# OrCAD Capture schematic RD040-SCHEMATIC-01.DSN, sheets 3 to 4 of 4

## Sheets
3 2: size A3
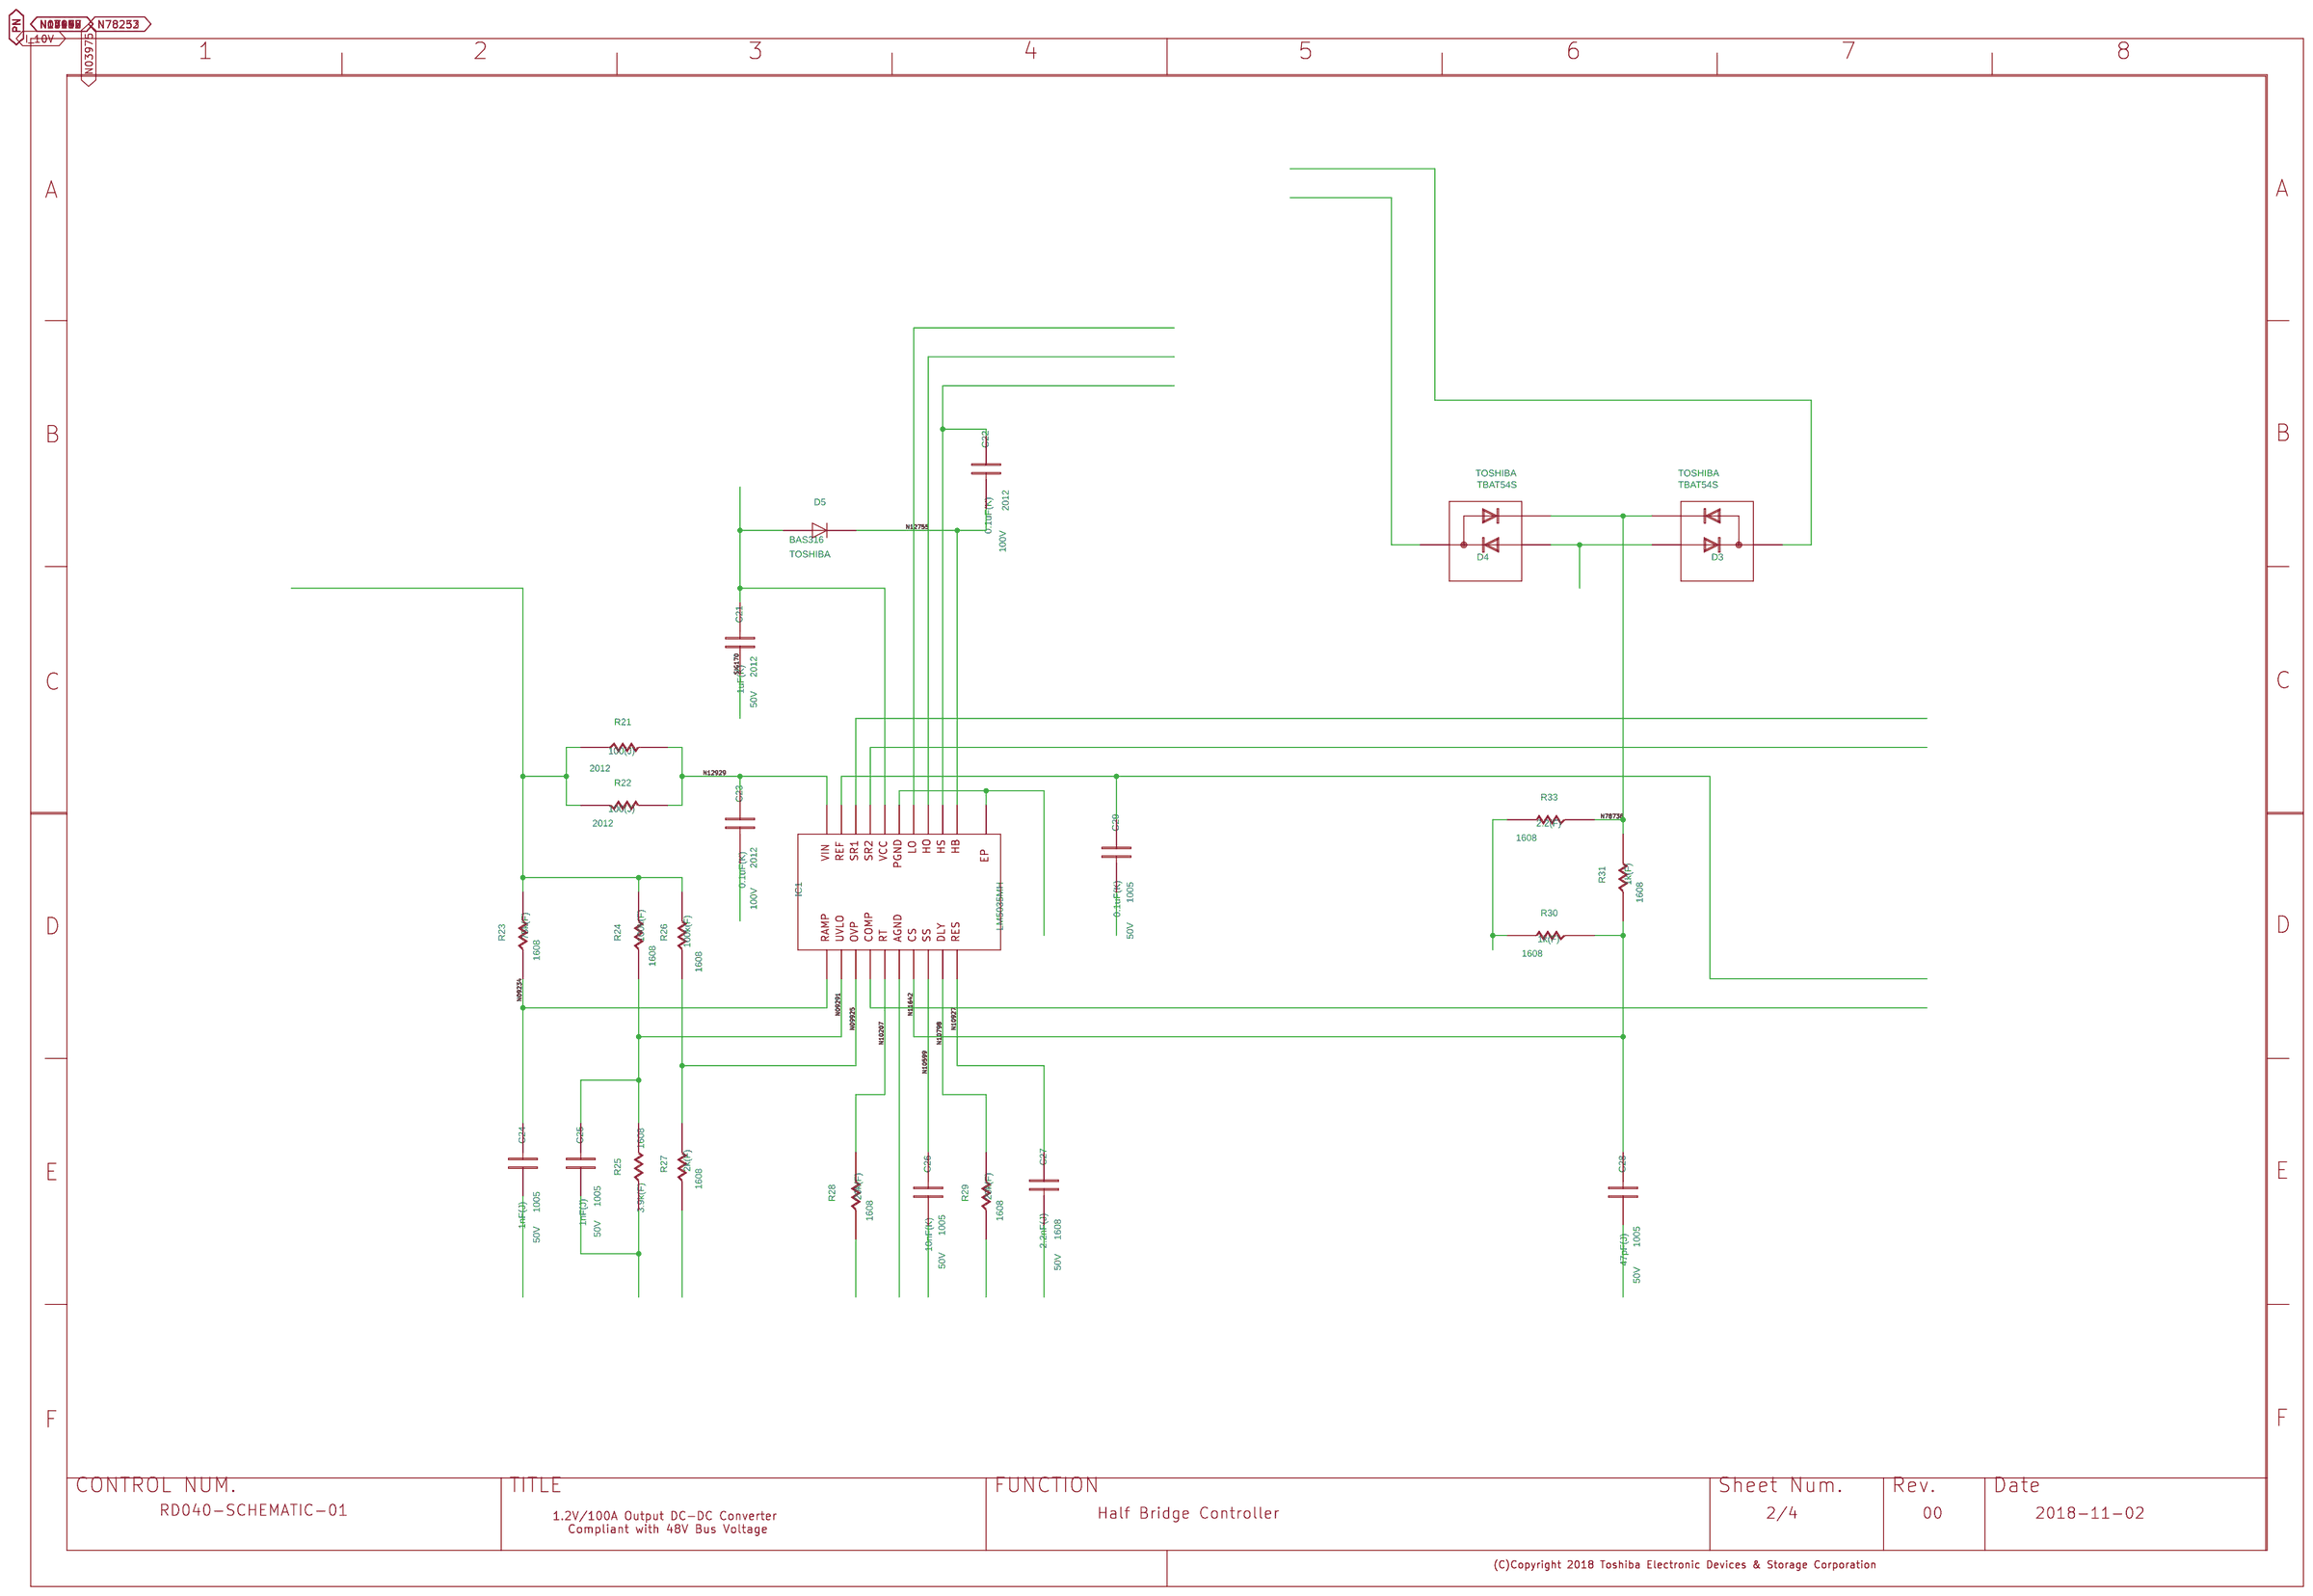
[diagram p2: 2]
4 1: size A3
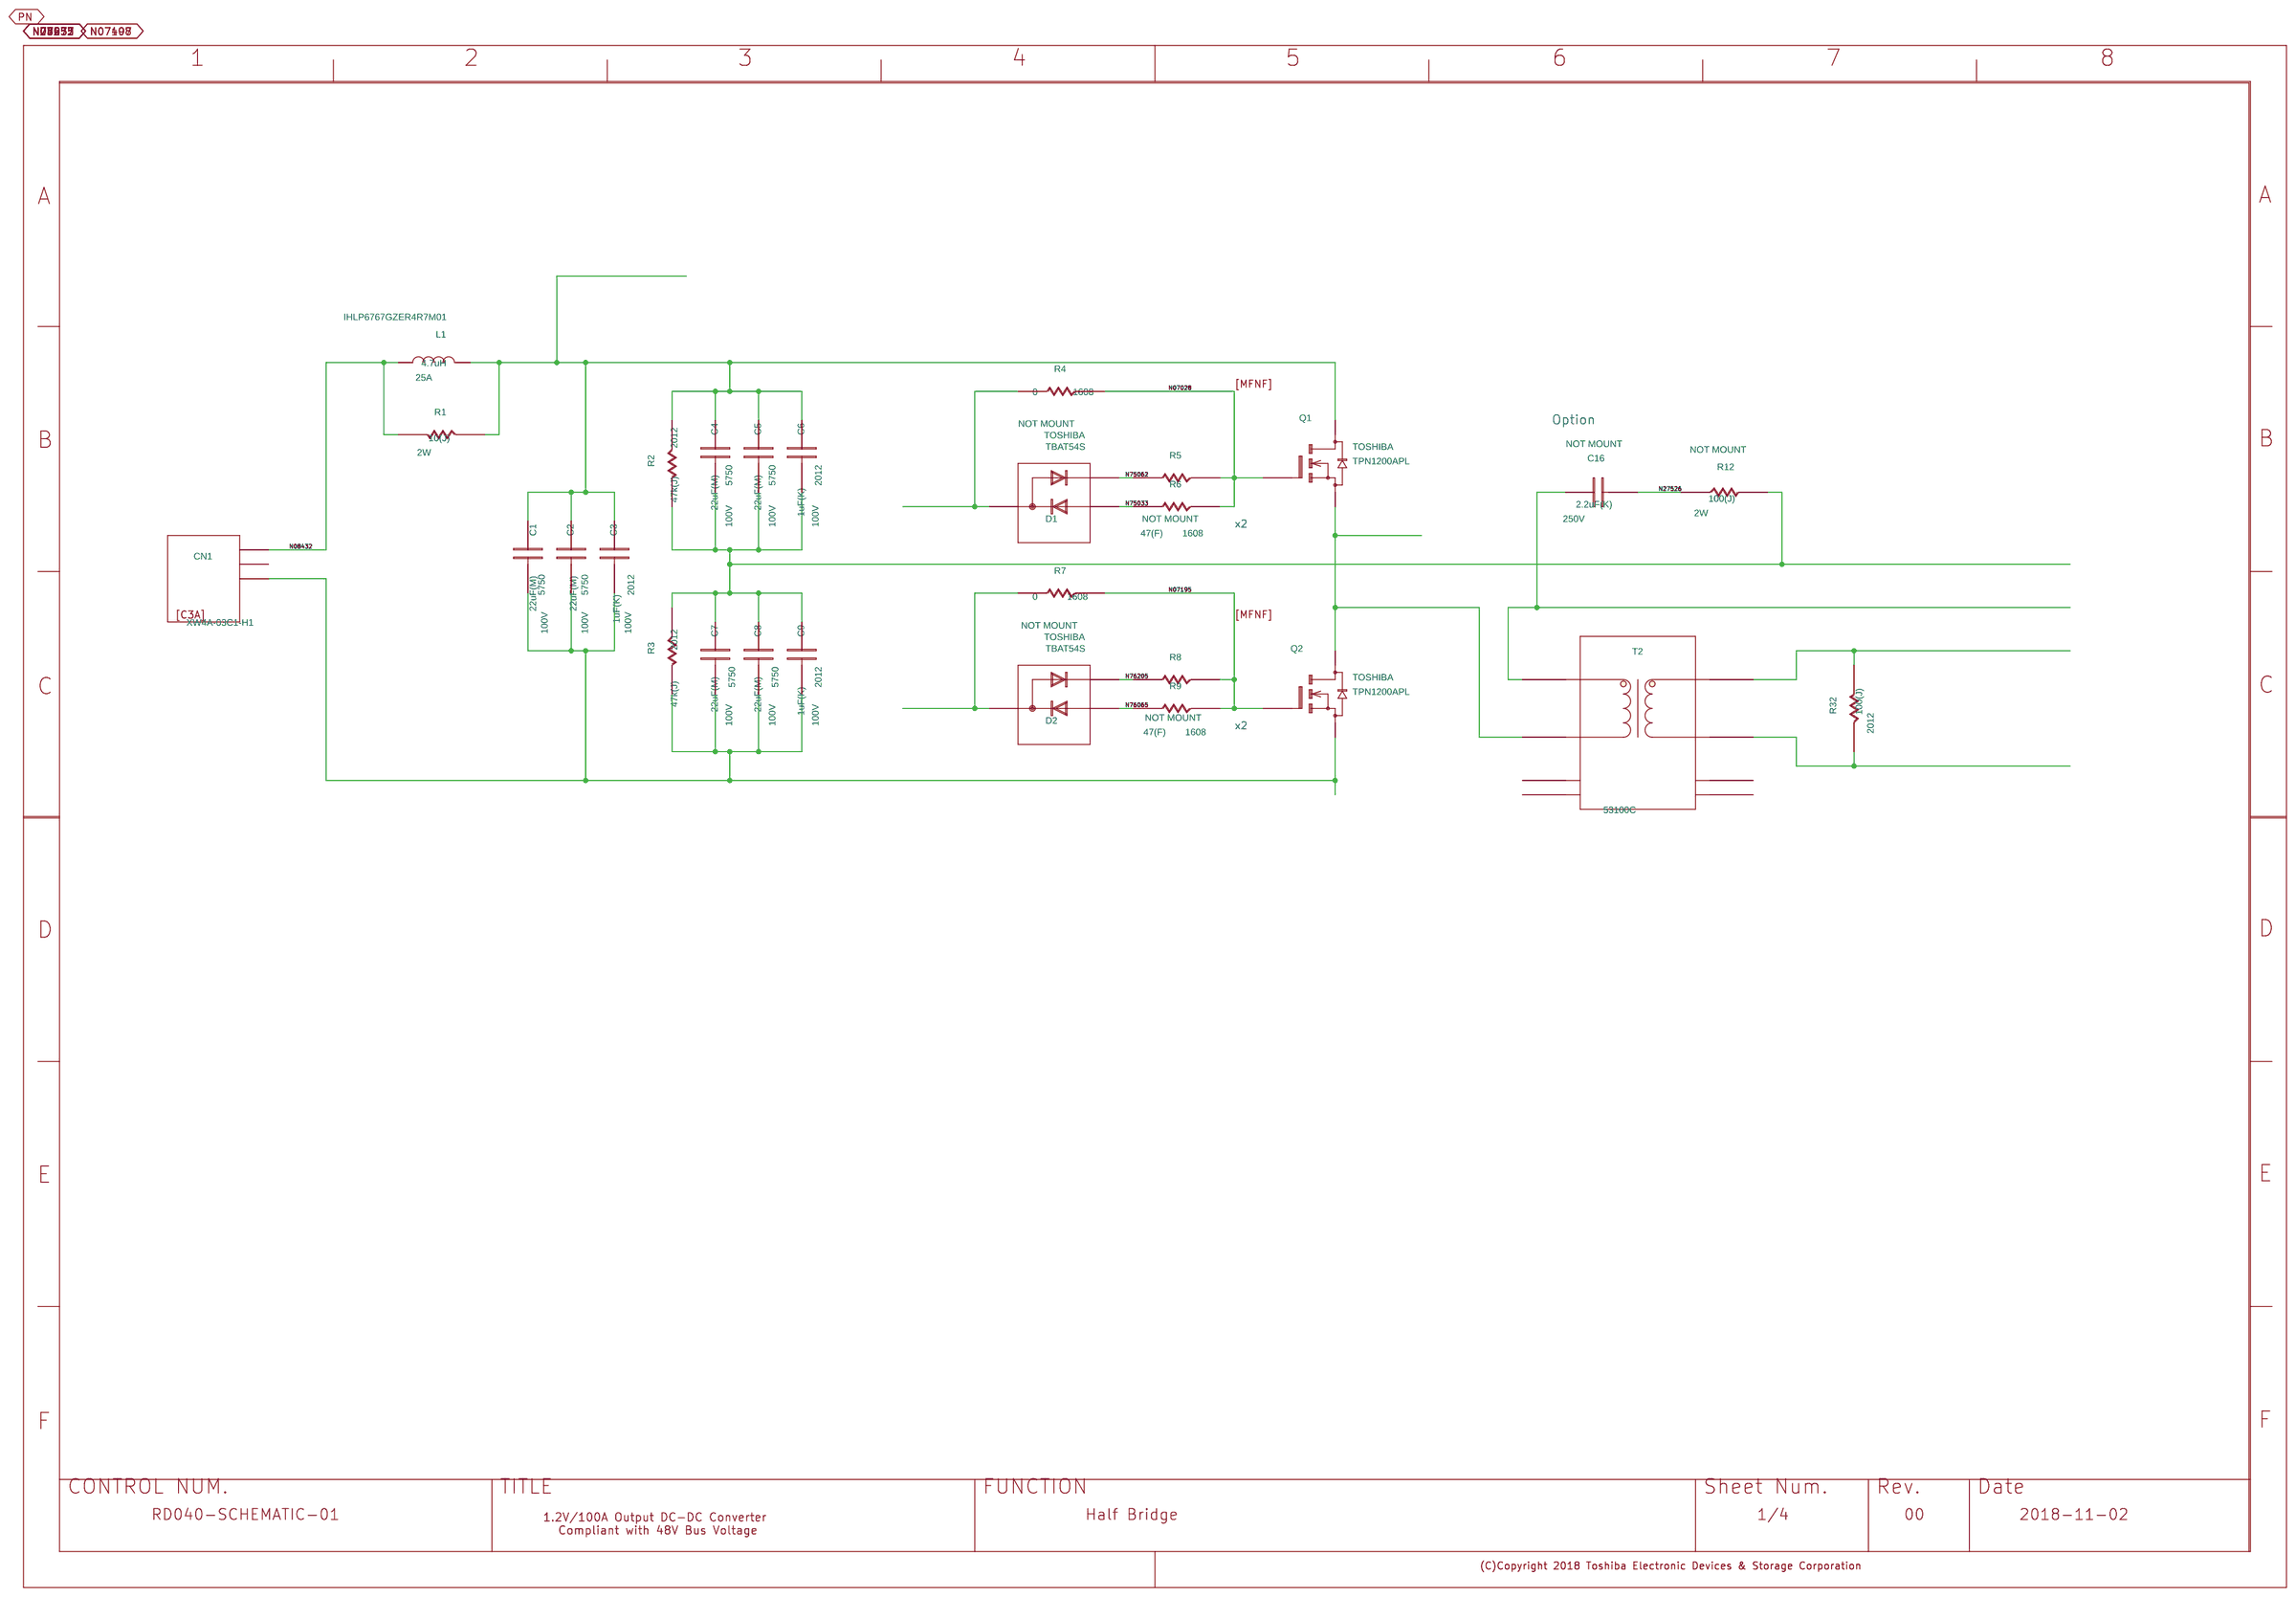
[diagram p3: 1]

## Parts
sheet 1
C1  22uF-M_100V  [CHIP-5750]
C2  22uF-M_100V  [CHIP-5750]
C3  1uF-K_100V  [CHIP-2012]
C4  22uF-M_100V  [CHIP-5750]
C5  22uF-M_100V  [CHIP-5750]
C6  1uF-K_100V  [CHIP-2012]
C7  22uF-M_100V  [CHIP-5750]
C8  22uF-M_100V  [CHIP-5750]
C9  1uF-K_100V  [CHIP-2012]
C16  C
CN1  XW4A-03C1-H1  [SIP-3]
D1  TBAT54S  [SOT23-3]
D2  TBAT54S  [SOT23-3]
L1  4u7H-M_6767  [SMD-6767]
Q1  TPN1200APL  [TSON-8]
Q2  TPN1200APL  [TSON-8]
R1  10-J_2W  [Axial-2]
R2  47k-J_2012  [CHIP-2012]
R3  47k-J_2012  [CHIP-2012]
R4  NM_1608  [CHIP-1608]
R5  47-F_1608  [CHIP-1608]
R6  47-F_1608  [CHIP-1608]
R7  NM_1608  [CHIP-1608]
R8  47-F_1608  [CHIP-1608]
R9  47-F_1608  [CHIP-1608]
R12  R
R32  100-J_2012  [CHIP-2012]
T2  CT_10A:10V
U?#3  WAKU_DEF100_2018
sheet 2
C21  1uF-K_2012  [CHIP-2012]
C22  0u1F-K_100V  [CHIP-2012]
C23  0u1F-K_100V  [CHIP-2012]
C24  1000pF-J_1005  [CHIP-1005]
C25  1000pF-J_1005  [CHIP-1005]
C26  10nF-J_1005  [CHIP-1005]
C27  2200pF-J_1608  [CHIP-1608]
C28  47pF-J_1005  [CHIP-1005]
C29  0u1F-K_1005  [CHIP-1005]
D3  TBAT54S  [SOT23-3]
D4  TBAT54S  [SOT23-3]
D5  BAS316  [CHIP-2012]
IC1  LM5035MH
R21  100-J_2012  [CHIP-2012]
R22  100-J_2012  [CHIP-2012]
R23  75k-F_1608  [CHIP-1608]
R24  100k-F_1608  [CHIP-1608]
R25  10k-F_1608  [CHIP-1608]
R26  100k-F_1608  [CHIP-1608]
R27  2k0-F_1608  [CHIP-1608]
R28  20k-F_1608  [CHIP-1608]
R29  20k-F_1608  [CHIP-1608]
R30  NM_1608  [CHIP-1608]
R31  1k0-F_1608  [CHIP-1608]
R33  22-F_1608  [CHIP-1608]
U?#2  WAKU_DEF100_2018

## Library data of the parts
C1 = C: AUTHOR: w20070dm; COMMENT: Chip-Capacitor(X7R),22uF-M,100V; COMPCOMMENT: 5750; COMPONENTNAME: C_C; COMPONENTTYPE: 4; DATE: 2018/09/12; INSTANCENAME: I04446; MAKER: Murata; NUMBER DEVICES IN PACKAGE: 1; PIN NAMES ROTATE: True; PIN NAMES VISIBLE: False; PIN NUMBERS VISIBLE: False; SAVECOUNT: 1; TIME: 16:59:57; TYPE: KRM55WR72A226M; UPDATEDATE: 2018/09/12; UPDATETIME: 16:59:57; UPDATEUSER: w20070dm; VAL1: 22uF(M); VAL2: 100V; VAL3: KRM55WR72A226M
C2 = C: AUTHOR: w20070dm; COMMENT: Chip-Capacitor(X7R),22uF-M,100V; COMPCOMMENT: 5750; COMPONENTNAME: C_C; COMPONENTTYPE: 4; DATE: 2018/09/12; INSTANCENAME: I04482; MAKER: Murata; NUMBER DEVICES IN PACKAGE: 1; PIN NAMES ROTATE: True; PIN NAMES VISIBLE: False; PIN NUMBERS VISIBLE: False; SAVECOUNT: 1; TIME: 16:59:57; TYPE: KRM55WR72A226M; UPDATEDATE: 2018/09/12; UPDATETIME: 16:59:57; UPDATEUSER: w20070dm; VAL1: 22uF(M); VAL2: 100V; VAL3: KRM55WR72A226M
C3 = C: AUTHOR: w20070dm; COMMENT: Chip-Capacitor(X7S),1uF-K,100V; COMPCOMMENT: 2012; COMPONENTNAME: C_C; COMPONENTTYPE: 4; DATE: 2018/09/12; INSTANCENAME: I04414; MAKER: Murata; NUMBER DEVICES IN PACKAGE: 1; PIN NAMES ROTATE: True; PIN NAMES VISIBLE: False; PIN NUMBERS VISIBLE: False; SAVECOUNT: 1; TIME: 16:59:57; TYPE: GRM21BC72A105K; UPDATEDATE: 2018/09/12; UPDATETIME: 16:59:57; UPDATEUSER: w20070dm; VAL1: 1uF(K); VAL2: 100V; VAL3: GRM21BC72A105K
C4 = C: AUTHOR: w20070dm; COMMENT: Chip-Capacitor(X7R),22uF-M,100V; COMPCOMMENT: 5750; COMPONENTNAME: C_C; COMPONENTTYPE: 4; DATE: 2018/09/12; INSTANCENAME: I60867; MAKER: Murata; NUMBER DEVICES IN PACKAGE: 1; PIN NAMES ROTATE: True; PIN NAMES VISIBLE: False; PIN NUMBERS VISIBLE: False; SAVECOUNT: 1; TIME: 16:59:57; TYPE: KRM55WR72A226M; UPDATEDATE: 2018/09/12; UPDATETIME: 16:59:57; UPDATEUSER: w20070dm; VAL1: 22uF(M); VAL2: 100V; VAL3: KRM55WR72A226M
C5 = C: AUTHOR: w20070dm; COMMENT: Chip-Capacitor(X7R),22uF-M,100V; COMPCOMMENT: 5750; COMPONENTNAME: C_C; COMPONENTTYPE: 4; DATE: 2018/09/12; INSTANCENAME: I60839; MAKER: Murata; NUMBER DEVICES IN PACKAGE: 1; PIN NAMES ROTATE: True; PIN NAMES VISIBLE: False; PIN NUMBERS VISIBLE: False; SAVECOUNT: 1; TIME: 16:59:57; TYPE: KRM55WR72A226M; UPDATEDATE: 2018/09/12; UPDATETIME: 16:59:57; UPDATEUSER: w20070dm; VAL1: 22uF(M); VAL2: 100V; VAL3: KRM55WR72A226M
C6 = C: AUTHOR: w20070dm; COMMENT: Chip-Capacitor(X7S),1uF-K,100V; COMPCOMMENT: 2012; COMPONENTNAME: C_C; COMPONENTTYPE: 4; DATE: 2018/09/12; INSTANCENAME: I60803; MAKER: Murata; NUMBER DEVICES IN PACKAGE: 1; PIN NAMES ROTATE: True; PIN NAMES VISIBLE: False; PIN NUMBERS VISIBLE: False; SAVECOUNT: 1; TIME: 16:59:57; TYPE: GRM21BC72A105K; UPDATEDATE: 2018/09/12; UPDATETIME: 16:59:57; UPDATEUSER: w20070dm; VAL1: 1uF(K); VAL2: 100V; VAL3: GRM21BC72A105K
C7 = C: AUTHOR: w20070dm; COMMENT: Chip-Capacitor(X7R),22uF-M,100V; COMPCOMMENT: 5750; COMPONENTNAME: C_C; COMPONENTTYPE: 4; DATE: 2018/09/12; INSTANCENAME: I61562; MAKER: Murata; NUMBER DEVICES IN PACKAGE: 1; PIN NAMES ROTATE: True; PIN NAMES VISIBLE: False; PIN NUMBERS VISIBLE: False; SAVECOUNT: 1; TIME: 16:59:57; TYPE: KRM55WR72A226M; UPDATEDATE: 2018/09/12; UPDATETIME: 16:59:57; UPDATEUSER: w20070dm; VAL1: 22uF(M); VAL2: 100V; VAL3: KRM55WR72A226M
C8 = C: AUTHOR: w20070dm; COMMENT: Chip-Capacitor(X7R),22uF-M,100V; COMPCOMMENT: 5750; COMPONENTNAME: C_C; COMPONENTTYPE: 4; DATE: 2018/09/12; INSTANCENAME: I61642; MAKER: Murata; NUMBER DEVICES IN PACKAGE: 1; PIN NAMES ROTATE: True; PIN NAMES VISIBLE: False; PIN NUMBERS VISIBLE: False; SAVECOUNT: 1; TIME: 16:59:57; TYPE: KRM55WR72A226M; UPDATEDATE: 2018/09/12; UPDATETIME: 16:59:57; UPDATEUSER: w20070dm; VAL1: 22uF(M); VAL2: 100V; VAL3: KRM55WR72A226M
C9 = C: AUTHOR: w20070dm; COMMENT: Chip-Capacitor(X7S),1uF-K,100V; COMPCOMMENT: 2012; COMPONENTNAME: C_C; COMPONENTTYPE: 4; DATE: 2018/09/12; INSTANCENAME: I61594; MAKER: Murata; NUMBER DEVICES IN PACKAGE: 1; PIN NAMES ROTATE: True; PIN NAMES VISIBLE: False; PIN NUMBERS VISIBLE: False; SAVECOUNT: 1; TIME: 16:59:57; TYPE: GRM21BC72A105K; UPDATEDATE: 2018/09/12; UPDATETIME: 16:59:57; UPDATEUSER: w20070dm; VAL1: 1uF(K); VAL2: 100V; VAL3: GRM21BC72A105K
C16 = C: COMPONENTTYPE: 4; NOTMOUNT: NOT MOUNT; VAL1: 2.2uF(K); VAL2: 250V; VAL3: ECQE2225KB
CN1 = C3A: COMMENT: Terminal-Block(3pin,250V12A); COMPONENTNAME: PIN-HEADER_3x1_PIN-HEADER_3x1.Normal_package; COMPONENTTYPE: 4; FUNCTION: PIN-HEADER_3x1_PIN-HEADER_3x1.Normal_package; INSTANCENAME: I08244; MAKER: Omron; NUMBER DEVICES IN PACKAGE: 1; PARTNAME: PIN-HEADER_3x1; PIN NAMES ROTATE: True; PIN NAMES VISIBLE: False; PIN NUMBERS VISIBLE: True
D1 = DML: COMMENT: Schottky-barrier-diode(Dual,30V200mA); COMPONENTNAME: 1SS226_1SS226.Normal_package; COMPONENTTYPE: 4; FUNCTION: 1SS226_1SS226.Normal_package; INSTANCENAME: I71543; MAKER: Toshiba; NOTMOUNT: NOT MOUNT; NUMBER DEVICES IN PACKAGE: 1; PARTNAME: 1SS226; PIN NAMES ROTATE: True; PIN NAMES VISIBLE: False; PIN NUMBERS VISIBLE: True; USERCOMPTEXT3: TOSHIBA
D2 = DML: COMMENT: Schottky-barrier-diode(Dual,30V200mA); COMPONENTNAME: 1SS226_1SS226.Normal_package; COMPONENTTYPE: 4; FUNCTION: 1SS226_1SS226.Normal_package; INSTANCENAME: I78427; MAKER: Toshiba; NOTMOUNT: NOT MOUNT; NUMBER DEVICES IN PACKAGE: 1; PARTNAME: 1SS226; PIN NAMES ROTATE: True; PIN NAMES VISIBLE: False; PIN NUMBERS VISIBLE: True; USERCOMPTEXT3: TOSHIBA
L1 = L: AUTHOR: w20070dm; COMMENT: Inductor(4.7uH25A); COMPONENTNAME: INDUCTOR_INDUCTOR; COMPONENTTYPE: 4; DATE: 2018/09/12; INSTANCENAME: I20636496; MAKER: Vishay; NUMBER DEVICES IN PACKAGE: 1; ORDER: 0; PARTNAME: INDUCTOR; PIN NAMES ROTATE: True; PIN NAMES VISIBLE: False; PIN NUMBERS VISIBLE: False; SAVECOUNT: 1; TIME: 16:59:57; TYPE: IHLP6767GZER4R7M01; UPDATEDATE: 2018/09/12; UPDATETIME: 16:59:57; UPDATEUSER: w20070dm; VAL1: 4.7uH; VAL2: 25A; VAL3: IHLP6767GZER4R7M01
Q1 = MFNF: AUTHOR: w20070dm; COMMENT: MOS-FET(n-ch,100V40A); COMPONENTNAME: MOSFET_N(D)_MOSFET_N(D).Normal_package; COMPONENTTYPE: 4; DATE: 2018/09/12; FUNCTION: MOSFET_N(D)_MOSFET_N(D).Normal_package; INSTANCENAME: I69029; MAKER: Toshiba; NUMBER DEVICES IN PACKAGE: 1; PARTNAME: MOSFET_N(D); PIN NAMES ROTATE: True; PIN NAMES VISIBLE: False; PIN NUMBERS VISIBLE: True; TIME: 16:59:57; UPDATEDATE: 2018/09/12; UPDATETIME: 16:59:57; UPDATEUSER: w20070dm; USERCOMPTEXT3: TOSHIBA
Q2 = MFNF: AUTHOR: w20070dm; COMMENT: MOS-FET(n-ch,100V40A); COMPONENTNAME: MOSFET_N(D)_MOSFET_N(D).Normal_package; COMPONENTTYPE: 4; DATE: 2018/09/12; FUNCTION: MOSFET_N(D)_MOSFET_N(D).Normal_package; INSTANCENAME: I69405; MAKER: Toshiba; NUMBER DEVICES IN PACKAGE: 1; PARTNAME: MOSFET_N(D); PIN NAMES ROTATE: True; PIN NAMES VISIBLE: False; PIN NUMBERS VISIBLE: True; TIME: 16:59:57; UPDATEDATE: 2018/09/12; UPDATETIME: 16:59:57; UPDATEUSER: w20070dm; USERCOMPTEXT3: TOSHIBA
R1 = R: AUTHOR: w20070dm; COMMENT: Metal-Film-Resister,10ohm-J,2W; COMPONENTNAME: R_R; COMPONENTTYPE: 4; DATE: 2018/09/12; INSTANCENAME: I62527; MAKER: ROHM; NUMBER DEVICES IN PACKAGE: 1; PIN NAMES ROTATE: True; PIN NAMES VISIBLE: False; PIN NUMBERS VISIBLE: False; SAVECOUNT: 1; TIME: 16:59:57; TYPE: MOS2CT52A100J; UPDATEDATE: 2018/09/12; UPDATETIME: 16:59:57; UPDATEUSER: w20070dm; VAL1: 10(J); VAL2: 2W; VAL3: MOS2CT52A100J
R2 = R: AUTHOR: w20070dm; COMMENT: Chip-Resister(anti-surge),47k-J,0.4W; COMPCOMMENT: 2012; COMPONENTNAME: R_R; COMPONENTTYPE: 4; DATE: 2018/09/12; INSTANCENAME: I20654113; MAKER: ROHM; NUMBER DEVICES IN PACKAGE: 1; PIN NAMES ROTATE: True; PIN NAMES VISIBLE: False; PIN NUMBERS VISIBLE: False; SAVECOUNT: 1; TIME: 16:59:57; TYPE: ESR10EZPJ473; UPDATEDATE: 2018/09/12; UPDATETIME: 16:59:57; UPDATEUSER: w20070dm; VAL1: 47k(J); VAL2: 0.4W; VAL3: ESR10EZPJ473
R3 = R: AUTHOR: w20070dm; COMMENT: Chip-Resister(anti-surge),47k-J,0.4W; COMPCOMMENT: 2012; COMPONENTNAME: R_R; COMPONENTTYPE: 4; DATE: 2018/09/12; INSTANCENAME: I61482; MAKER: ROHM; NUMBER DEVICES IN PACKAGE: 1; PIN NAMES ROTATE: True; PIN NAMES VISIBLE: False; PIN NUMBERS VISIBLE: False; SAVECOUNT: 1; TIME: 16:59:57; TYPE: ESR10EZPJ473; UPDATEDATE: 2018/09/12; UPDATETIME: 16:59:57; UPDATEUSER: w20070dm; VAL1: 47k(J); VAL2: 0.4W; VAL3: ESR10EZPJ473
R4 = R: AUTHOR: w20070dm; COMMENT: Chip-Resistor,10ohm-F(100ppm),1/10W; COMPCOMMENT: 1608; COMPONENTNAME: R_R; COMPONENTTYPE: 4; DATE: 2018/09/12; INSTANCENAME: I75159; MAKER: KOA; NUMBER DEVICES IN PACKAGE: 1; PIN NAMES ROTATE: True; PIN NAMES VISIBLE: False; PIN NUMBERS VISIBLE: False; SAVECOUNT: 1; TIME: 16:59:57; TYPE: RK73H1JTTD10R0F; UPDATEDATE: 2018/09/12; UPDATETIME: 16:59:57; UPDATEUSER: w20070dm; VAL1: 0; VAL2: 1/8W; VAL3: MCR03EZHJ000
R5 = R: AUTHOR: w20070dm; COMMENT: Chip-Resistor,47ohm-F(100ppm),1/10W; COMPCOMMENT: 1608; COMPONENTNAME: R_R; COMPONENTTYPE: 4; DATE: 2018/09/12; INSTANCENAME: I74967; MAKER: KOA; NOTMOUNT: NOT MOUNT; NUMBER DEVICES IN PACKAGE: 1; PIN NAMES ROTATE: True; PIN NAMES VISIBLE: False; PIN NUMBERS VISIBLE: False; SAVECOUNT: 1; TIME: 16:59:57; TYPE: RK73H1JTTD47R0F; UPDATEDATE: 2018/09/12; UPDATETIME: 16:59:57; UPDATEUSER: w20070dm; VAL1: 47(F); VAL3: RK73H1JTTD47R0F
R6 = R: AUTHOR: w20070dm; COMMENT: Chip-Resistor,47ohm-F(100ppm),1/10W; COMPCOMMENT: 1608; COMPONENTNAME: R_R; COMPONENTTYPE: 4; DATE: 2018/09/12; INSTANCENAME: I74991; MAKER: KOA; NOTMOUNT: NOT MOUNT; NUMBER DEVICES IN PACKAGE: 1; PIN NAMES ROTATE: True; PIN NAMES VISIBLE: False; PIN NUMBERS VISIBLE: False; SAVECOUNT: 1; TIME: 16:59:57; TYPE: RK73H1JTTD47R0F; UPDATEDATE: 2018/09/12; UPDATETIME: 16:59:57; UPDATEUSER: w20070dm; VAL1: 47(F); VAL3: RK73H1JTTD47R0F
R7 = R: AUTHOR: w20070dm; COMMENT: Chip-Resistor,10ohm-F(100ppm),1/10W; COMPCOMMENT: 1608; COMPONENTNAME: R_R; COMPONENTTYPE: 4; DATE: 2018/09/12; INSTANCENAME: I76137; MAKER: KOA; NUMBER DEVICES IN PACKAGE: 1; PIN NAMES ROTATE: True; PIN NAMES VISIBLE: False; PIN NUMBERS VISIBLE: False; SAVECOUNT: 1; TIME: 16:59:57; TYPE: RK73H1JTTD10R0F; UPDATEDATE: 2018/09/12; UPDATETIME: 16:59:57; UPDATEUSER: w20070dm; VAL1: 0; VAL2: 1/8W; VAL3: MCR03EZHJ000
R8 = R: AUTHOR: w20070dm; COMMENT: Chip-Resistor,47ohm-F(100ppm),1/10W; COMPCOMMENT: 1608; COMPONENTNAME: R_R; COMPONENTTYPE: 4; DATE: 2018/09/12; INSTANCENAME: I76161; MAKER: KOA; NOTMOUNT: NOT MOUNT; NUMBER DEVICES IN PACKAGE: 1; PIN NAMES ROTATE: True; PIN NAMES VISIBLE: False; PIN NUMBERS VISIBLE: False; SAVECOUNT: 1; TIME: 16:59:57; TYPE: RK73H1JTTD47R0F; UPDATEDATE: 2018/09/12; UPDATETIME: 16:59:57; UPDATEUSER: w20070dm; VAL1: 47(F); VAL3: RK73H1JTTD47R0F
R9 = R: AUTHOR: w20070dm; COMMENT: Chip-Resistor,47ohm-F(100ppm),1/10W; COMPCOMMENT: 1608; COMPONENTNAME: R_R; COMPONENTTYPE: 4; DATE: 2018/09/12; INSTANCENAME: I76085; MAKER: KOA; NOTMOUNT: NOT MOUNT; NUMBER DEVICES IN PACKAGE: 1; PIN NAMES ROTATE: True; PIN NAMES VISIBLE: False; PIN NUMBERS VISIBLE: False; SAVECOUNT: 1; TIME: 16:59:57; TYPE: RK73H1JTTD47R0F; UPDATEDATE: 2018/09/12; UPDATETIME: 16:59:57; UPDATEUSER: w20070dm; VAL1: 47(F); VAL3: RK73H1JTTD47R0F
R12 = R: COMPONENTTYPE: 4; NOTMOUNT: NOT MOUNT; VAL1: 100(J); VAL2: 2W; VAL3: MOS2CT52A101J
R32 = R: AUTHOR: w20070dm; COMMENT: Chip-Resister(anti-surge),100ohm-J,0.4W; COMPCOMMENT: 2012; COMPONENTNAME: R_R; COMPONENTTYPE: 4; DATE: 2018/09/12; INSTANCENAME: I78881; MAKER: ROHM; NUMBER DEVICES IN PACKAGE: 1; PIN NAMES ROTATE: True; PIN NAMES VISIBLE: False; PIN NUMBERS VISIBLE: False; SAVECOUNT: 1; TIME: 16:59:57; TYPE: ESR10EZPJ101; UPDATEDATE: 2018/09/12; UPDATETIME: 16:59:57; UPDATEUSER: w20070dm; VAL1: 100(J); VAL3: ESR10EZPJ101
T2 = 53100C: COMMENT: Current-Transformer(10Amax,1A:1V@100ohm); COMPONENTNAME: AF-TRANS(2B_murata)_AF-TRANS(2B_murata).Normal_package; COMPONENTTYPE: 4; FUNCTION: AF-TRANS(2B_murata)_AF-TRANS(2B_murata).Normal_package; INSTANCENAME: I67135; MAKER: Murata; NUMBER DEVICES IN PACKAGE: 1; ORDER: 0; PARTNAME: AF-TRANS(2B_murata); PIN NAMES ROTATE: True; PIN NAMES VISIBLE: False; PIN NUMBERS VISIBLE: True
U?#3 = WAKU_DEF100_2018: COMPONENTTYPE: 2; DATE: 2018-11-02; DRAWINGNUMBER: RD040-SCHEMATIC-01; FUNCTION: Half Bridge; REVISION: 00; SAVEAREA0: -45080,-4508,463680,304612; SHEETNUMBER: 1/4; TIME: 14:09:12; TITLE: 1.2V/100A Output DC-DC Converter / Compliant with 48V Bus Voltage; UPDATEDATE: 2018/11/05; UPDATETIME: 09:58:42
C21 = C: AUTHOR: w20070dm; COMMENT: Chip-Capacitor(X7R),1uF-K,50V; COMPCOMMENT: 2012; COMPONENTNAME: C_C; COMPONENTTYPE: 4; DATE: 2018/09/12; INSTANCENAME: I16847; MAKER: Murata; NUMBER DEVICES IN PACKAGE: 1; PIN NAMES ROTATE: True; PIN NAMES VISIBLE: False; PIN NUMBERS VISIBLE: False; SAVECOUNT: 1; TIME: 16:59:57; TYPE: GCM21BR71H105K; UPDATEDATE: 2018/09/12; UPDATETIME: 16:59:57; UPDATEUSER: w20070dm; VAL1: 1uF(K); VAL2: 50V; VAL3: GCM21BR71H105K
C22 = C: AUTHOR: w20070dm; COMMENT: Chip-Capacitor(X7R),0.1uF-K,100V; COMPCOMMENT: 2012; COMPONENTNAME: C_C; COMPONENTTYPE: 4; DATE: 2018/09/12; INSTANCENAME: I12586; MAKER: Murata; NUMBER DEVICES IN PACKAGE: 1; PIN NAMES ROTATE: True; PIN NAMES VISIBLE: False; PIN NUMBERS VISIBLE: False; SAVECOUNT: 1; TIME: 16:59:57; TYPE: GRM21BR72A104K; UPDATEDATE: 2018/09/12; UPDATETIME: 16:59:57; UPDATEUSER: w20070dm; VAL1: 0.1uF(K); VAL2: 100V; VAL3: GRM21BR72A104K
C23 = C: AUTHOR: w20070dm; COMMENT: Chip-Capacitor(X7R),0.1uF-K,100V; COMPCOMMENT: 2012; COMPONENTNAME: C_C; COMPONENTTYPE: 4; DATE: 2018/09/12; INSTANCENAME: I13088; MAKER: Murata; NUMBER DEVICES IN PACKAGE: 1; PIN NAMES ROTATE: True; PIN NAMES VISIBLE: False; PIN NUMBERS VISIBLE: False; SAVECOUNT: 1; TIME: 16:59:57; TYPE: GRM21BR72A104K; UPDATEDATE: 2018/09/12; UPDATETIME: 16:59:57; UPDATEUSER: w20070dm; VAL1: 0.1uF(K); VAL2: 100V; VAL3: GRM21BR72A104K
C24 = C: AUTHOR: w20070dm; COMMENT: Chip-Capasitor(CH0),1000pF-J,50V; COMPCOMMENT: 1005; COMPONENTNAME: C_C; COMPONENTTYPE: 4; DATE: 2018/09/12; INSTANCENAME: I20645479; MAKER: MURATA; NUMBER DEVICES IN PACKAGE: 1; PIN NAMES ROTATE: True; PIN NAMES VISIBLE: False; PIN NUMBERS VISIBLE: False; SAVECOUNT: 1; TIME: 16:59:57; TYPE: GRM1552C1H102J; UPDATEDATE: 2018/09/12; UPDATETIME: 16:59:57; UPDATEUSER: w20070dm; VAL1: 1nF(J); VAL2: 50V; VAL3: GRM1552C1H102J
C25 = C: AUTHOR: w20070dm; COMMENT: Chip-Capasitor(CH0),1000pF-J,50V; COMPCOMMENT: 1005; COMPONENTNAME: C_C; COMPONENTTYPE: 4; DATE: 2018/09/12; INSTANCENAME: I09708; MAKER: MURATA; NUMBER DEVICES IN PACKAGE: 1; PIN NAMES ROTATE: True; PIN NAMES VISIBLE: False; PIN NUMBERS VISIBLE: False; SAVECOUNT: 1; TIME: 16:59:57; TYPE: GRM1552C1H102J; UPDATEDATE: 2018/09/12; UPDATETIME: 16:59:57; UPDATEUSER: w20070dm; VAL1: 1nF(J); VAL2: 50V; VAL3: GRM1552C1H102J
C26 = C: AUTHOR: w20070dm; COMMENT: Chip-Capasitor(X7R),10nF-K,50V; COMPCOMMENT: 1005; COMPONENTNAME: C_C; COMPONENTTYPE: 4; DATE: 2018/09/12; INSTANCENAME: I10622; MAKER: MURATA; NUMBER DEVICES IN PACKAGE: 1; PIN NAMES ROTATE: True; PIN NAMES VISIBLE: False; PIN NUMBERS VISIBLE: False; SAVECOUNT: 1; TIME: 16:59:57; TYPE: GCM155R11H103K; UPDATEDATE: 2018/09/12; UPDATETIME: 16:59:57; UPDATEUSER: w20070dm; VAL1: 10nF(K); VAL2: 50V; VAL3: GCM155R11H103K
C27 = C: AUTHOR: w20070dm; COMMENT: Chip-Capasitor(CH0),2200pF-J,50V; COMPCOMMENT: 1608; COMPONENTNAME: C_C; COMPONENTTYPE: 4; DATE: 2018/09/12; INSTANCENAME: I79432; MAKER: MURATA; NUMBER DEVICES IN PACKAGE: 1; PIN NAMES ROTATE: True; PIN NAMES VISIBLE: False; PIN NUMBERS VISIBLE: False; SAVECOUNT: 1; TIME: 16:59:57; TYPE: GRM1882C1H222J; UPDATEDATE: 2018/09/12; UPDATETIME: 16:59:57; UPDATEUSER: w20070dm; VAL1: 2.2nF(J); VAL2: 50V; VAL3: GRM1882C1H222J
C28 = C: AUTHOR: w20070dm; COMMENT: Chip-Capasitor(CH0),47pF-J,50V; COMPCOMMENT: 1005; COMPONENTNAME: C_C; COMPONENTTYPE: 4; DATE: 2018/09/12; INSTANCENAME: I10408; MAKER: MURATA; NUMBER DEVICES IN PACKAGE: 1; PIN NAMES ROTATE: True; PIN NAMES VISIBLE: False; PIN NUMBERS VISIBLE: False; SAVECOUNT: 1; TIME: 16:59:57; TYPE: GRM1552C1H470J; UPDATEDATE: 2018/09/12; UPDATETIME: 16:59:57; UPDATEUSER: w20070dm; VAL1: 47pF(J); VAL2: 50V; VAL3: GRM1552C1H470J
C29 = C: AUTHOR: w20070dm; COMMENT: Chip-Capacitor(X7R),0.1uF-K,50V; COMPCOMMENT: 1005; COMPONENTNAME: C_C; COMPONENTTYPE: 4; DATE: 2018/09/12; INSTANCENAME: I82167; MAKER: Murata; NUMBER DEVICES IN PACKAGE: 1; PIN NAMES ROTATE: True; PIN NAMES VISIBLE: False; PIN NUMBERS VISIBLE: False; SAVECOUNT: 1; TIME: 16:59:57; TYPE: GCM155R71H104K; UPDATEDATE: 2018/09/12; UPDATETIME: 16:59:57; UPDATEUSER: w20070dm; VAL1: 0.1uF(K); VAL2: 50V; VAL3: GCM155R71H104K
D3 D4 = DML: COMMENT: Schottky-barrier-diode(Dual,30V200mA); COMPONENTNAME: 1SS226_1SS226.Normal_package; COMPONENTTYPE: 4; FUNCTION: 1SS226_1SS226.Normal_package; INSTANCENAME: I78476; MAKER: Toshiba; NUMBER DEVICES IN PACKAGE: 1; PARTNAME: 1SS226; PIN NAMES ROTATE: True; PIN NAMES VISIBLE: False; PIN NUMBERS VISIBLE: True; USERCOMPTEXT3: TOSHIBA
D5 = D: COMMENT: SW-Diode(100V250mA); COMPONENTNAME: DIODE_DIODE; COMPONENTTYPE: 4; INSTANCENAME: I31395; MAKER: Toshiba; NUMBER DEVICES IN PACKAGE: 1; PARTNAME: DIODE; PIN NAMES ROTATE: True; PIN NAMES VISIBLE: False; PIN NUMBERS VISIBLE: False; USERCOMPTEXT3: TOSHIBA
IC1 = LM5035MH: COMPONENTTYPE: 4
R21 = R: AUTHOR: w20070dm; COMMENT: Chip-Resister(anti-surge),100ohm-J,0.4W; COMPCOMMENT: 2012; COMPONENTNAME: R_R; COMPONENTTYPE: 4; DATE: 2018/09/12; INSTANCENAME: I13412; MAKER: ROHM; NUMBER DEVICES IN PACKAGE: 1; PIN NAMES ROTATE: True; PIN NAMES VISIBLE: False; PIN NUMBERS VISIBLE: False; SAVECOUNT: 1; TIME: 16:59:57; TYPE: ESR10EZPJ101; UPDATEDATE: 2018/09/12; UPDATETIME: 16:59:57; UPDATEUSER: w20070dm; VAL1: 100(J); VAL2: 0.4W; VAL3: ESR10EZPJ101
R22 = R: AUTHOR: w20070dm; COMMENT: Chip-Resister(anti-surge),100ohm-J,0.4W; COMPCOMMENT: 2012; COMPONENTNAME: R_R; COMPONENTTYPE: 4; DATE: 2018/09/12; INSTANCENAME: I13353; MAKER: ROHM; NUMBER DEVICES IN PACKAGE: 1; PIN NAMES ROTATE: True; PIN NAMES VISIBLE: False; PIN NUMBERS VISIBLE: False; SAVECOUNT: 1; TIME: 16:59:57; TYPE: ESR10EZPJ101; UPDATEDATE: 2018/09/12; UPDATETIME: 16:59:57; UPDATEUSER: w20070dm; VAL1: 100(J); VAL3: ESR10EZPJ101
R23 = R: AUTHOR: w20070dm; COMMENT: Chip-Resistor,75k-F(100ppm),1/10W; COMPCOMMENT: 1608; COMPONENTNAME: R_R; COMPONENTTYPE: 4; DATE: 2018/09/12; INSTANCENAME: I20641644; MAKER: KOA; NUMBER DEVICES IN PACKAGE: 1; PIN NAMES ROTATE: True; PIN NAMES VISIBLE: False; PIN NUMBERS VISIBLE: False; SAVECOUNT: 1; TIME: 16:59:57; TYPE: RK73H1JTTD7502F; UPDATEDATE: 2018/09/12; UPDATETIME: 16:59:57; UPDATEUSER: w20070dm; VAL1: 75k(F); VAL3: RK73H1JTTD7502F
R24 = R: AUTHOR: w20070dm; COMMENT: Chip-Resistor,100k-F(100ppm),1/10W; COMPCOMMENT: 1608; COMPONENTNAME: R_R; COMPONENTTYPE: 4; DATE: 2018/09/12; INSTANCENAME: I09414; MAKER: KOA; NUMBER DEVICES IN PACKAGE: 1; PIN NAMES ROTATE: True; PIN NAMES VISIBLE: False; PIN NUMBERS VISIBLE: False; SAVECOUNT: 1; TIME: 16:59:57; TYPE: RK73H1JTTD1003F; UPDATEDATE: 2018/09/12; UPDATETIME: 16:59:57; UPDATEUSER: w20070dm; VAL1: 100k(F); VAL3: RK73H1JTTD1003F
R25 = R: AUTHOR: w20070dm; COMMENT: Chip-Resistor,10k-F(100ppm),1/10W; COMPCOMMENT: 1608; COMPONENTNAME: R_R; COMPONENTTYPE: 4; DATE: 2018/09/12; INSTANCENAME: I09474; MAKER: KOA; NUMBER DEVICES IN PACKAGE: 1; PIN NAMES ROTATE: True; PIN NAMES VISIBLE: False; PIN NUMBERS VISIBLE: False; SAVECOUNT: 1; TIME: 16:59:57; TYPE: RK73H1JTTD1002F; UPDATEDATE: 2018/09/12; UPDATETIME: 16:59:57; UPDATEUSER: w20070dm; VAL1: 3.9k(F); VAL2: 1/10W; VAL3: RK73H1JTTD3901F
R26 = R: AUTHOR: w20070dm; COMMENT: Chip-Resistor,100k-F(100ppm),1/10W; COMPCOMMENT: 1608; COMPONENTNAME: R_R; COMPONENTTYPE: 4; DATE: 2018/09/12; INSTANCENAME: I09859; MAKER: KOA; NUMBER DEVICES IN PACKAGE: 1; PIN NAMES ROTATE: True; PIN NAMES VISIBLE: False; PIN NUMBERS VISIBLE: False; SAVECOUNT: 1; TIME: 16:59:57; TYPE: RK73H1JTTD1003F; UPDATEDATE: 2018/09/12; UPDATETIME: 16:59:57; UPDATEUSER: w20070dm; VAL1: 100k(F); VAL3: RK73H1JTTD1003F
R27 = R: AUTHOR: w20070dm; COMMENT: Chip-Resistor,2k0-F(100ppm),1/10W; COMPCOMMENT: 1608; COMPONENTNAME: R_R; COMPONENTTYPE: 4; DATE: 2018/09/12; INSTANCENAME: I09883; MAKER: KOA; NUMBER DEVICES IN PACKAGE: 1; PIN NAMES ROTATE: True; PIN NAMES VISIBLE: False; PIN NUMBERS VISIBLE: False; SAVECOUNT: 1; TIME: 16:59:57; TYPE: RK73H1JTTD2001F; UPDATEDATE: 2018/09/12; UPDATETIME: 16:59:57; UPDATEUSER: w20070dm; VAL1: 2k(F); VAL2: 1/10W; VAL3: RK73H1JTTD2001F
R28 = R: AUTHOR: w20070dm; COMMENT: Chip-Resistor,20k-F(100ppm),1/10W; COMPCOMMENT: 1608; COMPONENTNAME: R_R; COMPONENTTYPE: 4; DATE: 2018/09/12; INSTANCENAME: I10331; MAKER: KOA; NUMBER DEVICES IN PACKAGE: 1; PIN NAMES ROTATE: True; PIN NAMES VISIBLE: False; PIN NUMBERS VISIBLE: False; SAVECOUNT: 1; TIME: 16:59:57; TYPE: RK73H1JTTD2002F; UPDATEDATE: 2018/09/12; UPDATETIME: 16:59:57; UPDATEUSER: w20070dm; VAL1: 20k(F); VAL2: 1/10W; VAL3: RK73H1JTTD2002F
R29 = R: AUTHOR: w20070dm; COMMENT: Chip-Resistor,20k-F(100ppm),1/10W; COMPCOMMENT: 1608; COMPONENTNAME: R_R; COMPONENTTYPE: 4; DATE: 2018/09/12; INSTANCENAME: I10792; MAKER: KOA; NUMBER DEVICES IN PACKAGE: 1; PIN NAMES ROTATE: True; PIN NAMES VISIBLE: False; PIN NUMBERS VISIBLE: False; SAVECOUNT: 1; TIME: 16:59:57; TYPE: RK73H1JTTD2002F; UPDATEDATE: 2018/09/12; UPDATETIME: 16:59:57; UPDATEUSER: w20070dm; VAL1: 20k(F); VAL2: 1/10W; VAL3: RK73H1JTTD2002F
R30 = R: AUTHOR: w20070dm; COMMENT: Chip-Resistor,1k0-F(100ppm),1/10W; COMPCOMMENT: 1608; COMPONENTNAME: R_R; COMPONENTTYPE: 4; DATE: 2018/09/12; INSTANCENAME: I79043; MAKER: KOA; NUMBER DEVICES IN PACKAGE: 1; PIN NAMES ROTATE: True; PIN NAMES VISIBLE: False; PIN NUMBERS VISIBLE: False; SAVECOUNT: 1; TIME: 16:59:57; TYPE: RK73H1JTTD1001F; UPDATEDATE: 2018/09/12; UPDATETIME: 16:59:57; UPDATEUSER: w20070dm; VAL1: 1k(F); VAL2: 1/10W; VAL3: RK73H1JTTD1001F
R31 = R: AUTHOR: w20070dm; COMMENT: Chip-Resistor,1k0-F(100ppm),1/10W; COMPCOMMENT: 1608; COMPONENTNAME: R_R; COMPONENTTYPE: 4; DATE: 2018/09/12; INSTANCENAME: I12478; MAKER: KOA; NUMBER DEVICES IN PACKAGE: 1; PIN NAMES ROTATE: True; PIN NAMES VISIBLE: False; PIN NUMBERS VISIBLE: False; SAVECOUNT: 1; TIME: 16:59:57; TYPE: RK73H1JTTD1001F; UPDATEDATE: 2018/09/12; UPDATETIME: 16:59:57; UPDATEUSER: w20070dm; VAL1: 1k(F); VAL2: 1/10W; VAL3: RK73H1JTTD1001F
R33 = R: AUTHOR: w20070dm; COMMENT: Chip-Resistor,22ohm-F(100ppm),1/10W; COMPCOMMENT: 1608; COMPONENTNAME: R_R; COMPONENTTYPE: 4; DATE: 2018/09/12; INSTANCENAME: I113731; MAKER: KOA; NUMBER DEVICES IN PACKAGE: 1; PIN NAMES ROTATE: True; PIN NAMES VISIBLE: False; PIN NUMBERS VISIBLE: False; SAVECOUNT: 1; TIME: 16:59:57; TYPE: RK73H1JTTD22R0F; UPDATEDATE: 2018/09/12; UPDATETIME: 16:59:57; UPDATEUSER: w20070dm; VAL1: 2.2(F); VAL2: 1/10W; VAL3: RK73H1JTTD22R0F
U?#2 = WAKU_DEF100_2018: COMPONENTTYPE: 2; DATE: 2018-11-02; DRAWINGNUMBER: RD040-SCHEMATIC-01; FUNCTION: Half Bridge Controller; REVISION: 00; SAVEAREA0: -45080,-4508,463680,304612; SHEETNUMBER: 2/4; TIME: 13:53:51; TITLE: 1.2V/100A Output DC-DC Converter / Compliant with 48V Bus Voltage; UPDATEDATE: 2018/11/05; UPDATETIME: 09:58:42

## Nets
I_10V: C21.2 D5.A IC1.16 ; also on sheet 2
PN: C1.2 C2.2 C3.2 C7.2 C8.2 C9.2 C21.1 C23.2 C24.1 C25.1 C26.1 C27.2 C28.1 C29.2 CN1.1 D3.1 D4.1 IC1.6 IC1.15 IC1.21 Q2.S R3.1 R25.2 R27.2 R28.2 R29.2 R30.1 R33.1 ; also on sheet 1 2
N03975: C1.1 C2.1 C3.1 C4.1 C5.1 C6.1 L1.2 Q1.D R1.2 R2.2 R21.2 R22.2 R23.1 R24.1 R26.1
N04057: C4.2 C5.2 C6.2 C7.1 C8.1 C9.1 R2.1 R3.2 R12.1 ; also on sheet 2
N07028: Q1.G R4.2 R5.2 R6.2
N07195: Q2.G R7.2 R8.2 R9.2
N07198: D1.3 IC1.13 R4.1
N07407: D2.3 IC1.14 R7.1
N07475: C22.1 IC1.12 Q1.S Q2.D T2.8
N08432: CN1.3 L1.1 R1.1
N09234: C24.2 IC1.1 R23.2
N09291: C25.2 IC1.2 R24.2 R25.1
N09925: IC1.3 R26.2 R27.1
N10150: IC1.4 ; also on sheet 1
N10207: IC1.5 R28.1
N10599: C26.2 IC1.8
N10798: IC1.9 R29.1
N10927: C27.1 IC1.10
N11642: C28.2 IC1.7 R30.2 R31.2
N12755: C22.2 D5.C IC1.11
N12929: C23.1 IC1.20 R21.1 R22.1
N13908: C29.1 IC1.19 ; also on sheet 1
N14012: IC1.18 ; also on sheet 1
N14069: IC1.17 ; also on sheet 1
N27526: C16.2 R12.2
N27553: C16.1 T2.7 ; also on sheet 2
N75033: D1.1 R6.1
N75062: D1.2 R5.1
N76065: D2.1 R9.1
N76205: D2.2 R8.1
N78233: D4.3 R32.1 T2.1
N78252: D3.3 R32.2 T2.3
N78738: D3.2 D4.2 R31.1 R33.2

Not connected (* = marked no-connect by the designer): CN1 2; T2 2 4 5 6

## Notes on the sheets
sheet 4
- Option
- x2
- x2
